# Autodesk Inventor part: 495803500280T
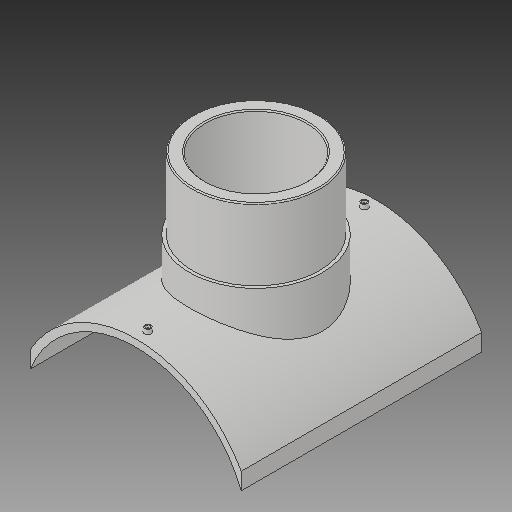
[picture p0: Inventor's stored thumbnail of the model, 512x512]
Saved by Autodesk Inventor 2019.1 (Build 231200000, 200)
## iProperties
Created: 2017-10
Part Number: 495803500280T
Material: Generic
Description: PLASSON BRANCH SADDLE  500x280
Document SubType Name: Modeling
Designer: KIM
Mass: 2754.05 g
Surface Area: 3037.44 cm^2
Volume: 2754.05 cm^3
Density: 1 g/cm^3
Appearance: Default
Author: KIM
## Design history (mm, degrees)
derived "495803.ipt"
feature "Solid1::495803.ipt"
tag "TaggingFeature1"
body "Solid1"
other parameters: "d1" = 16, "d2" = 465, "d4" = 0, "d12" = 275.6, "d13" = 14, "d14" = 238.5, "d16" = 5 deg, "d18" = 4, "d19" = 14, "d20" = 0, "d21" = 3, "d22" = 0, "d23" = 491, "d24" = 294, "d25" = 16, "d26" = 224, "d28" = 0, "d29" = 9.6, "d31" = 0, "d32" = 112.5, "d33" = 0, "d34" = 5, "d37" = 157.5, "d38" = 0, "d39" = 2.5, "B_" = 465, "H_" = 225, "x_" = 16, "D_" = 16
